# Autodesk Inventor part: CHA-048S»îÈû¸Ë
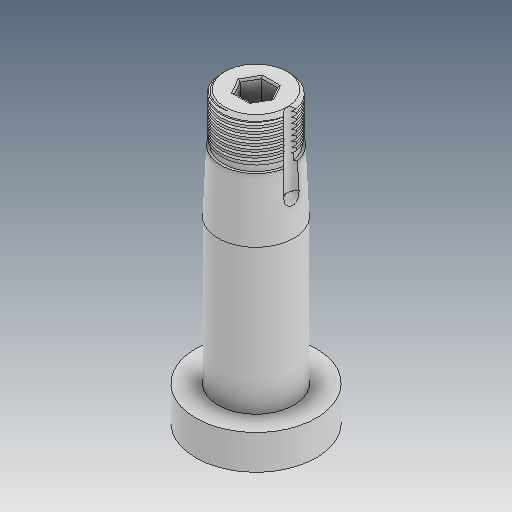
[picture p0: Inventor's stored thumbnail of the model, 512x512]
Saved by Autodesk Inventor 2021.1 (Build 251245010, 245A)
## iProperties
Created: 2019-05
Part Number: CHA-048S»îÈû¸Ë
Material: Ogólny
Document SubType Name: Modeling
Designer: user
Density: 1 g/cm^3
Appearance: Domyślna
Author: user
Revision Number: ÈÎºÎ
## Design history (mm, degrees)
feature "ÊäÈë1"
node "Bryła1"
